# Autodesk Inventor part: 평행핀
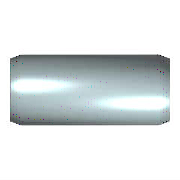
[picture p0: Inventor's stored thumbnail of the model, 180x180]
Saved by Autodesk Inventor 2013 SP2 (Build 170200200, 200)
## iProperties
IsCustomPart: 0
Created: 2009-02
Part Number: 평행핀
Material: 강, 연강
Description: 평행 핀
Document SubType Name: Modeling
Standard: KS B 1320
Designer: KYOUNG IL JANG
Standards Organization: KS
Language: ko-KR
Size Designation: B 5 x  20
Categories: <MemberInstance><Categories><Category DisplayName="조임쇠" InternalName="e4da775c-781d-43d5-af7c-5136215cf5a6" Mnemonic="FSTN"><Category DisplayName="핀" InternalNa
Density: 1 g/cm^3
Author: KYOUNG IL JANG
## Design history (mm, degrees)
sketch "스케치"
  geometry: C1 r 2.5 at (0, 0); 1 further point
  constraints: 1 centre point, 1 coincident
  dimensions: "d1" = 5 diameter of C1 (= NND)
extrude "본체" new body sketch "스케치" distance "d2" = 20 (= NLG); taper "d3" = 0 deg
chamfer "스케치2" distance "d8" = 0.8 (= PHH); stored, may be unused: angle "d9" = 15 deg (= FAWI), second distance "d12" = 0.8 (= PHH)
body "Solid1"
chamfer "모따기1" distance "d4" = 0.8 (= PHH); stored, may be unused: angle "d5" = 15 deg (= FAWI), second distance "d11" = 0.8 (= PHH)
other parameters: "NND" = 5 [user parameter; used in 1 equation term], "NLG" = 20 [user parameter; used in 1 equation term], "PHH" = 0.8 [user parameter; used in 4 equation terms], "FAWI" = 15 deg [user parameter; used in 2 equation terms], "d13" = 0, "d15" = 0, "d16" = 0, "KAH" = 0.63 [user parameter]
